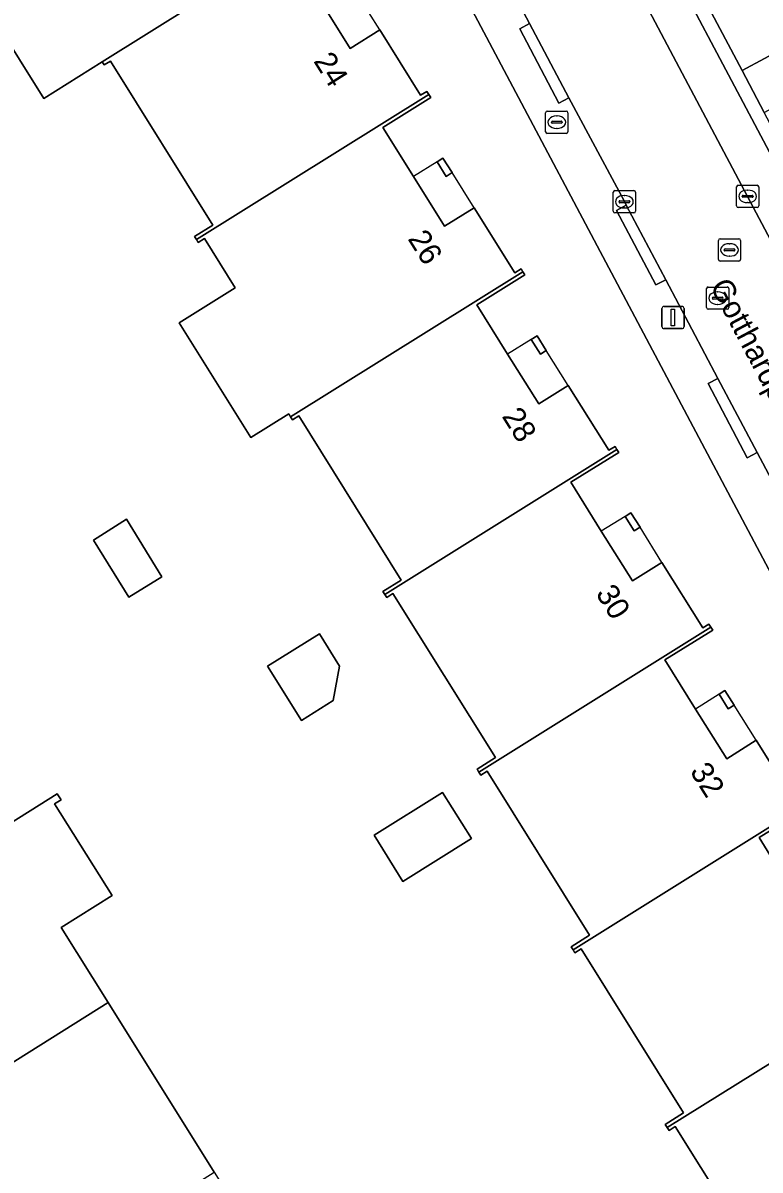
# Model space of a CAD drawing. Extents: x 158835 to 160077, y 386387 to 387778.
# Drawn here: x 159192.9 to 159226, y 387064.3 to 387115.8 of the extents above; entities that cross this region are included whole.
import ezdxf

# ---------------------------------------------------------------- set-up
doc = ezdxf.new("R2010")
doc.units = 0
for name, color, linetype in [('IMGEO_Berm_groen', 7, 'Continuous'), ('IMGEO_Brandkraan', 7, 'Continuous'), ('IMGEO_Erf', 7, 'Continuous'), ('IMGEO_Kolk', 7, 'Continuous'), ('IMGEO_Lichtmast', 7, 'Continuous'), ('IMGEO_Openbare_ruimte_label', 7, 'Continuous'), ('IMGEO_Pand', 7, 'Continuous'), ('IMGEO_Pand_nummerreeks', 7, 'Continuous'), ('IMGEO_Pand_overbouw', 7, 'Continuous'), ('IMGEO_Parkeervlak_open', 7, 'Continuous'), ('IMGEO_Rijbaan_lokaal_open', 7, 'Continuous'), ('IMGEO_Rioolput', 7, 'Continuous'), ('IMGEO_Voetpad_open', 7, 'Continuous')]:
    doc.layers.add(name, color=color, linetype=linetype)

msp = doc.modelspace()

# ---------------------------------------------------------------- linework, layer by layer
at = {"layer": 'IMGEO_Berm_groen'}
msp.add_lwpolyline([(159216.131, 387145.48), (159209.987, 387142.226), (159225.151, 387113.68), (159231.17, 387116.927), (159223.64, 387131.346), (159223.201, 387131.121)], close=True, dxfattribs=at)
at = {"layer": 'IMGEO_Brandkraan'}
for p, q in [((159216.334, 387110.937), (159216.334, 387111.789)), ((159216.409, 387111.863), (159217.261, 387111.863)), ((159217.335, 387111.789), (159217.335, 387110.937)), ((159216.593, 387111.357), (159216.593, 387111.369)), ((159217.031, 387111.32), (159216.633, 387111.32)), ((159216.636, 387111.406), (159217.034, 387111.406)), ((159216.822, 387111.643), (159216.847, 387111.643)), ((159217.077, 387111.369), (159217.077, 387111.357)), ((159217.261, 387110.863), (159216.409, 387110.863)), ((159216.845, 387111.083), (159216.82, 387111.083))]:
    msp.add_line(p, q, dxfattribs=at)
for points in [[(159216.334, 387110.937), (159216.334, 387111.789)], [(159216.409, 387111.863), (159217.261, 387111.863)], [(159217.335, 387111.789), (159217.335, 387110.937)], [(159217.261, 387110.863), (159216.409, 387110.863)]]:
    msp.add_lwpolyline(points, dxfattribs=at)
for centre, radius, start, end in [((159216.411, 387111.787), 0.0765, 91.552, 178.448), ((159216.411, 387111.787), 0.0765, 91.552, 178.448), ((159217.259, 387111.787), 0.0765, 1.552, 88.448), ((159217.259, 387111.787), 0.0765, 1.552, 88.448), ((159216.633, 387111.366), 0.0403, 85.8775, 175.7526), ((159216.63, 387111.356), 0.0366, 178.938, 274.7102), ((159217.034, 387111.363), 0.043, 264.8664, 352.4533), ((159217.038, 387111.368), 0.0386, 1.7309, 96.639), ((159216.411, 387110.939), 0.0765, 181.552, 268.448), ((159216.411, 387110.939), 0.0765, 181.552, 268.448), ((159217.259, 387110.939), 0.0765, 271.552, 358.448), ((159217.259, 387110.939), 0.0765, 271.552, 358.448)]:
    msp.add_arc(centre, radius, start, end, dxfattribs=at)
for centre, major_axis, ratio, start_param, end_param in [((159216.821, 387111.363), (-0.387, 0.002), 0.722429, 4.712389, 7.853982), ((159216.846, 387111.363), (-0.39, 0.002), 0.717154, 1.570796, 4.712389)]:
    msp.add_ellipse(centre, major_axis=major_axis, ratio=ratio, start_param=start_param, end_param=end_param, dxfattribs=at)
at = {"layer": 'IMGEO_Erf'}
for points in [[(159261.184, 387025.643), (159192.812, 387154.528)], [(159226.754, 387058.936), (159222.155, 387066.296), (159221.875, 387066.121), (159221.79, 387066.257), (159221.706, 387066.393), (159222.528, 387066.907), (159217.929, 387074.267), (159217.649, 387074.093), (159217.564, 387074.229), (159217.48, 387074.364), (159218.302, 387074.878), (159213.703, 387082.238), (159213.424, 387082.064), (159213.339, 387082.199), (159213.254, 387082.335), (159214.077, 387082.849), (159209.477, 387090.209), (159209.198, 387090.035), (159209.113, 387090.17), (159209.028, 387090.306), (159209.851, 387090.82), (159205.252, 387098.181), (159204.972, 387098.006), (159204.887, 387098.141), (159204.802, 387098.277), (159203.098, 387097.212), (159199.882, 387102.359), (159202.4, 387103.933), (159201.023, 387106.138), (159200.743, 387105.963), (159200.658, 387106.098), (159200.573, 387106.234), (159201.396, 387106.748), (159196.797, 387114.109), (159196.517, 387113.934), (159196.432, 387114.069), (159193.809, 387112.427), (159190.511, 387117.696)], [(159206.171, 387116.92), (159207.566, 387114.677), (159208.886, 387115.502), (159210.724, 387112.57), (159211.004, 387112.746), (159211.089, 387112.61), (159211.174, 387112.474), (159209.03, 387111.133), (159210.408, 387108.929), (159211.8, 387106.699), (159213.121, 387107.524), (159214.954, 387104.604), (159215.233, 387104.779), (159215.318, 387104.644), (159215.403, 387104.509), (159213.246, 387103.169), (159214.623, 387100.952), (159216.029, 387098.724), (159217.35, 387099.549), (159219.171, 387096.643), (159219.449, 387096.817), (159219.533, 387096.682), (159219.618, 387096.547), (159217.463, 387095.204), (159218.83, 387093.008), (159220.236, 387090.78), (159221.556, 387091.605), (159223.385, 387088.671), (159223.665, 387088.845), (159223.75, 387088.709), (159223.834, 387088.574), (159221.679, 387087.231), (159223.057, 387085.03), (159224.463, 387082.802), (159225.784, 387083.627), (159227.624, 387080.693)], [(159191.861, 387079.631), (159194.412, 387081.226), (159194.581, 387080.955), (159194.293, 387080.775), (159196.869, 387076.656), (159194.589, 387075.23), (159196.693, 387071.865), (159201.459, 387064.245), (159206.24, 387056.6), (159211.01, 387048.972), (159215.782, 387041.343), (159220.557, 387033.707), (159225.323, 387026.087)], [(159228.074, 387080.597), (159225.925, 387079.268), (159227.285, 387077.052)]]:
    msp.add_lwpolyline(points, dxfattribs=at)
for points in [[(159211.459, 387109.587), (159211.722, 387109.751), (159212.131, 387109.099), (159211.869, 387108.934)], [(159215.69, 387101.614), (159215.953, 387101.778), (159216.362, 387101.126), (159216.099, 387100.961)], [(159220.165, 387093.837), (159220.572, 387093.184), (159220.309, 387093.02), (159219.902, 387093.673)], [(159196.033, 387092.602), (159197.513, 387093.545), (159199.109, 387090.966), (159197.617, 387090.043)], [(159207.085, 387086.96), (159206.803, 387085.418), (159205.368, 387084.521), (159203.852, 387086.948), (159206.182, 387088.405)], [(159224.386, 387085.855), (159224.795, 387085.203), (159224.533, 387085.038), (159224.123, 387085.691)], [(159211.703, 387081.291), (159213.002, 387079.213), (159209.929, 387077.293), (159208.631, 387079.371)]]:
    msp.add_lwpolyline(points, close=True, dxfattribs=at)
at = {"layer": 'IMGEO_Kolk'}
for p, q in [((159219.369, 387107.368), (159219.369, 387108.22)), ((159219.444, 387108.294), (159220.296, 387108.294)), ((159220.37, 387108.22), (159220.37, 387107.368)), ((159224.903, 387107.609), (159224.903, 387108.461)), ((159224.978, 387108.535), (159225.83, 387108.535)), ((159225.391, 387108.315), (159225.416, 387108.315)), ((159225.904, 387108.461), (159225.904, 387107.609)), ((159219.628, 387107.788), (159219.628, 387107.8)), ((159220.066, 387107.751), (159219.668, 387107.751)), ((159219.671, 387107.837), (159220.069, 387107.837)), ((159219.857, 387108.074), (159219.882, 387108.074)), ((159220.112, 387107.8), (159220.112, 387107.788)), ((159225.162, 387108.029), (159225.162, 387108.041)), ((159225.6, 387107.992), (159225.202, 387107.992)), ((159225.205, 387108.078), (159225.603, 387108.078)), ((159225.414, 387107.755), (159225.389, 387107.755)), ((159225.646, 387108.041), (159225.646, 387108.029)), ((159220.296, 387107.294), (159219.444, 387107.294)), ((159219.88, 387107.514), (159219.855, 387107.514)), ((159225.83, 387107.535), (159224.978, 387107.535))]:
    msp.add_line(p, q, dxfattribs=at)
for points in [[(159219.369, 387107.368), (159219.369, 387108.22)], [(159219.444, 387108.294), (159220.296, 387108.294)], [(159220.37, 387108.22), (159220.37, 387107.368)], [(159224.903, 387107.609), (159224.903, 387108.461)], [(159224.978, 387108.535), (159225.83, 387108.535)], [(159225.904, 387108.461), (159225.904, 387107.609)], [(159220.296, 387107.294), (159219.444, 387107.294)], [(159225.83, 387107.535), (159224.978, 387107.535)]]:
    msp.add_lwpolyline(points, dxfattribs=at)
for centre, radius, start, end in [((159219.446, 387108.218), 0.0765, 91.552, 178.448), ((159219.446, 387108.218), 0.0765, 91.552, 178.448), ((159220.294, 387108.218), 0.0765, 1.552, 88.448), ((159220.294, 387108.218), 0.0765, 1.552, 88.448), ((159224.98, 387108.459), 0.0765, 91.552, 178.448), ((159224.98, 387108.459), 0.0765, 91.552, 178.448), ((159225.828, 387108.459), 0.0765, 1.552, 88.448), ((159225.828, 387108.459), 0.0765, 1.552, 88.448), ((159219.668, 387107.797), 0.0403, 85.8775, 175.7526), ((159219.665, 387107.787), 0.0366, 178.938, 274.7102), ((159220.069, 387107.794), 0.043, 264.8664, 352.4533), ((159220.073, 387107.799), 0.0386, 1.7309, 96.639), ((159224.98, 387107.611), 0.0765, 181.552, 268.448), ((159224.98, 387107.611), 0.0765, 181.552, 268.448), ((159225.202, 387108.038), 0.0403, 85.8775, 175.7526), ((159225.199, 387108.028), 0.0366, 178.938, 274.7102), ((159225.603, 387108.035), 0.043, 264.8664, 352.4533), ((159225.607, 387108.04), 0.0386, 1.7309, 96.639), ((159225.828, 387107.611), 0.0765, 271.552, 358.448), ((159225.828, 387107.611), 0.0765, 271.552, 358.448), ((159219.446, 387107.37), 0.0765, 181.552, 268.448), ((159219.446, 387107.37), 0.0765, 181.552, 268.448), ((159220.294, 387107.37), 0.0765, 271.552, 358.448), ((159220.294, 387107.37), 0.0765, 271.552, 358.448)]:
    msp.add_arc(centre, radius, start, end, dxfattribs=at)
for centre, major_axis, ratio, start_param, end_param in [((159225.39, 387108.035), (-0.387, 0.002), 0.722429, 4.712389, 7.853982), ((159225.415, 387108.035), (-0.39, 0.002), 0.717154, 1.570796, 4.712389), ((159219.856, 387107.794), (-0.387, 0.002), 0.722429, 4.712389, 7.853982), ((159219.881, 387107.794), (-0.39, 0.002), 0.717154, 1.570796, 4.712389)]:
    msp.add_ellipse(centre, major_axis=major_axis, ratio=ratio, start_param=start_param, end_param=end_param, dxfattribs=at)
at = {"layer": 'IMGEO_Lichtmast'}
for p, q in [((159221.556, 387102.199), (159221.556, 387102.999)), ((159221.556, 387102.999), (159221.556, 387102.199)), ((159221.656, 387103.099), (159222.446, 387103.099)), ((159222.446, 387103.099), (159221.656, 387103.099)), ((159222.546, 387102.999), (159222.546, 387102.199)), ((159222.546, 387102.199), (159222.546, 387102.999)), ((159222.446, 387102.099), (159221.656, 387102.099)), ((159221.656, 387102.099), (159222.446, 387102.099))]:
    msp.add_line(p, q, dxfattribs=at)
msp.add_lwpolyline([(159221.976, 387102.974), (159222.126, 387102.974), (159222.126, 387102.224), (159221.976, 387102.224), (159221.976, 387102.974)], dxfattribs=at)
for centre, start, end in [((159221.656, 387102.999), 90, 180), ((159221.656, 387102.999), 90, 180), ((159222.446, 387102.999), 0, 90), ((159222.446, 387102.999), 360, 90), ((159221.656, 387102.199), 180, 270), ((159221.656, 387102.199), 180, 270), ((159222.446, 387102.199), 270, 0), ((159222.446, 387102.199), 270, 0)]:
    msp.add_arc(centre, 0.1, start, end, dxfattribs=at)
at = {"layer": 'IMGEO_Pand'}
for points in [[(159204.667, 387123.466), (159203.347, 387122.641), (159201.966, 387124.874), (159200.584, 387127.072), (159202.714, 387128.412), (159202.629, 387128.548), (159192.211, 387122.033), (159192.296, 387121.897), (159192.576, 387122.071), (159193.962, 387119.853), (159190.511, 387117.696), (159193.809, 387112.427), (159196.432, 387114.069), (159206.858, 387120.595), (159206.773, 387120.73), (159206.495, 387120.555)], [(159208.886, 387115.502), (159207.566, 387114.677), (159206.171, 387116.92), (159204.804, 387119.145), (159206.943, 387120.46), (159206.858, 387120.595), (159196.432, 387114.069), (159196.517, 387113.934), (159196.797, 387114.109), (159201.396, 387106.748), (159200.573, 387106.234), (159200.658, 387106.098), (159211.089, 387112.61), (159211.004, 387112.746), (159210.724, 387112.57)], [(159213.121, 387107.524), (159211.8, 387106.699), (159210.408, 387108.929), (159209.03, 387111.133), (159211.174, 387112.474), (159211.089, 387112.61), (159200.658, 387106.098), (159200.743, 387105.963), (159201.023, 387106.138), (159202.4, 387103.933), (159199.882, 387102.359), (159203.098, 387097.212), (159204.802, 387098.277), (159204.887, 387098.141), (159215.318, 387104.644), (159215.233, 387104.779), (159214.954, 387104.604)], [(159211.722, 387109.751), (159211.459, 387109.587), (159211.869, 387108.934), (159212.131, 387109.099)], [(159217.35, 387099.549), (159216.029, 387098.724), (159214.623, 387100.952), (159213.246, 387103.169), (159215.403, 387104.509), (159215.318, 387104.644), (159204.887, 387098.141), (159204.972, 387098.006), (159205.252, 387098.181), (159209.851, 387090.82), (159209.028, 387090.306), (159209.113, 387090.17), (159219.533, 387096.682), (159219.449, 387096.817), (159219.171, 387096.643)], [(159215.953, 387101.778), (159215.69, 387101.614), (159216.099, 387100.961), (159216.362, 387101.126)], [(159221.556, 387091.605), (159220.236, 387090.78), (159218.83, 387093.008), (159217.463, 387095.204), (159219.618, 387096.547), (159219.533, 387096.682), (159209.113, 387090.17), (159209.198, 387090.035), (159209.477, 387090.209), (159214.077, 387082.849), (159213.254, 387082.335), (159213.339, 387082.199), (159223.75, 387088.709), (159223.665, 387088.845), (159223.385, 387088.671)], [(159220.165, 387093.837), (159219.902, 387093.673), (159220.309, 387093.02), (159220.572, 387093.184)], [(159196.033, 387092.602), (159197.617, 387090.043), (159199.109, 387090.966), (159197.513, 387093.545)], [(159225.784, 387083.627), (159224.463, 387082.802), (159223.057, 387085.03), (159221.679, 387087.231), (159223.834, 387088.574), (159223.75, 387088.709), (159213.339, 387082.199), (159213.424, 387082.064), (159213.703, 387082.238), (159218.302, 387074.878), (159217.48, 387074.364), (159217.564, 387074.229), (159227.989, 387080.733), (159227.904, 387080.868), (159227.624, 387080.693)], [(159203.852, 387086.948), (159205.368, 387084.521), (159206.803, 387085.418), (159207.085, 387086.96), (159206.182, 387088.405)], [(159224.386, 387085.855), (159224.123, 387085.691), (159224.533, 387085.038), (159224.795, 387085.203)], [(159194.589, 387075.23), (159196.869, 387076.656), (159194.293, 387080.775), (159194.581, 387080.955), (159194.412, 387081.226), (159191.861, 387079.631), (159191.946, 387079.495), (159182.069, 387073.317), (159182.153, 387073.181), (159183.756, 387074.181), (159185.132, 387071.975), (159186.523, 387069.743), (159185.199, 387068.918), (159187.029, 387065.984), (159186.758, 387065.814), (159186.843, 387065.678), (159196.693, 387071.865)], [(159208.631, 387079.371), (159209.929, 387077.293), (159213.002, 387079.213), (159211.703, 387081.291)], [(159230.012, 387075.65), (159228.691, 387074.825), (159227.285, 387077.052), (159225.925, 387079.268), (159228.074, 387080.597), (159227.989, 387080.733), (159217.564, 387074.229), (159217.649, 387074.093), (159217.929, 387074.267), (159222.528, 387066.907), (159221.706, 387066.393), (159221.79, 387066.257), (159232.217, 387072.75), (159232.132, 387072.886), (159231.852, 387072.71)], [(159234.24, 387067.673), (159232.92, 387066.848), (159231.509, 387069.082), (159230.151, 387071.292), (159232.302, 387072.614), (159232.217, 387072.75), (159221.79, 387066.257), (159221.875, 387066.121), (159222.155, 387066.296), (159226.754, 387058.936), (159225.932, 387058.422), (159226.016, 387058.286), (159236.446, 387064.776), (159236.361, 387064.912), (159236.08, 387064.736)], [(159196.693, 387071.865), (159186.843, 387065.678), (159186.927, 387065.543), (159188.521, 387066.546), (159189.896, 387064.362), (159191.297, 387062.136), (159189.968, 387061.3), (159191.799, 387058.351), (159191.527, 387058.181), (159191.612, 387058.044), (159201.459, 387064.245)]]:
    msp.add_lwpolyline(points, close=True, dxfattribs=at)
at = {"layer": 'IMGEO_Pand_overbouw'}
for points in [[(159207.898, 387117.078), (159207.489, 387117.73), (159207.225, 387117.568), (159206.171, 387116.92), (159207.566, 387114.677), (159208.886, 387115.502)], [(159212.131, 387109.099), (159211.722, 387109.751), (159211.459, 387109.587), (159210.408, 387108.929), (159211.8, 387106.699), (159213.121, 387107.524)], [(159216.362, 387101.126), (159215.953, 387101.778), (159215.69, 387101.614), (159214.623, 387100.952), (159216.029, 387098.724), (159217.35, 387099.549)], [(159220.572, 387093.184), (159220.165, 387093.837), (159219.902, 387093.673), (159218.83, 387093.008), (159220.236, 387090.78), (159221.556, 387091.605)], [(159224.795, 387085.203), (159224.386, 387085.855), (159224.123, 387085.691), (159223.057, 387085.03), (159224.463, 387082.802), (159225.784, 387083.627)]]:
    msp.add_lwpolyline(points, close=True, dxfattribs=at)
at = {"layer": 'IMGEO_Parkeervlak_open'}
for points in [[(159268.384, 387030.839), (159217.085, 387127.542)], [(159216.713, 387124.427), (159225.399, 387108.034), (159237.811, 387084.633), (159248.115, 387065.172), (159257.979, 387046.591)]]:
    msp.add_lwpolyline(points, dxfattribs=at)
at = {"layer": 'IMGEO_Rijbaan_lokaal_open'}
for points in [[(159257.979, 387046.591), (159248.115, 387065.172), (159237.811, 387084.633), (159225.399, 387108.034), (159216.713, 387124.427)], [(159213.276, 387120.222), (159215.613, 387115.79), (159217.374, 387112.457), (159219.855, 387107.834), (159219.95, 387107.637), (159221.723, 387104.295), (159224.064, 387099.868), (159225.827, 387096.54), (159228.412, 387091.668), (159230.181, 387088.351), (159232.537, 387083.923), (159234.3, 387080.597), (159234.872, 387079.512), (159236.866, 387075.757), (159238.628, 387072.438), (159240.974, 387068.001), (159242.753, 387064.674), (159243.322, 387063.566)]]:
    msp.add_lwpolyline(points, dxfattribs=at)
at = {"layer": 'IMGEO_Rioolput'}
for p, q in [((159224.087, 387105.206), (159224.087, 387106.058)), ((159224.162, 387106.132), (159225.014, 387106.132)), ((159225.088, 387106.058), (159225.088, 387105.206)), ((159224.346, 387105.626), (159224.346, 387105.638)), ((159224.784, 387105.589), (159224.386, 387105.589)), ((159224.389, 387105.675), (159224.787, 387105.675)), ((159224.575, 387105.912), (159224.6, 387105.912)), ((159224.83, 387105.638), (159224.83, 387105.626)), ((159225.014, 387105.132), (159224.162, 387105.132)), ((159224.598, 387105.352), (159224.573, 387105.352)), ((159223.557, 387103.042), (159223.557, 387103.894)), ((159223.632, 387103.968), (159224.484, 387103.968)), ((159223.859, 387103.511), (159224.257, 387103.511)), ((159224.045, 387103.748), (159224.07, 387103.748)), ((159224.558, 387103.894), (159224.558, 387103.042)), ((159224.484, 387102.968), (159223.632, 387102.968)), ((159223.816, 387103.462), (159223.816, 387103.474)), ((159224.254, 387103.425), (159223.856, 387103.425)), ((159224.068, 387103.188), (159224.043, 387103.188)), ((159224.3, 387103.474), (159224.3, 387103.462))]:
    msp.add_line(p, q, dxfattribs=at)
for points in [[(159224.087, 387105.206), (159224.087, 387106.058)], [(159224.162, 387106.132), (159225.014, 387106.132)], [(159225.088, 387106.058), (159225.088, 387105.206)], [(159225.014, 387105.132), (159224.162, 387105.132)], [(159223.557, 387103.042), (159223.557, 387103.894)], [(159223.632, 387103.968), (159224.484, 387103.968)], [(159224.558, 387103.894), (159224.558, 387103.042)], [(159224.484, 387102.968), (159223.632, 387102.968)]]:
    msp.add_lwpolyline(points, dxfattribs=at)
for centre, radius, start, end in [((159224.164, 387106.056), 0.0765, 91.552, 178.448), ((159224.164, 387106.056), 0.0765, 91.552, 178.448), ((159225.012, 387106.056), 0.0765, 1.552, 88.448), ((159225.012, 387106.056), 0.0765, 1.552, 88.448), ((159224.386, 387105.635), 0.0403, 85.8775, 175.7526), ((159224.383, 387105.625), 0.0366, 178.938, 274.7102), ((159224.787, 387105.632), 0.043, 264.8664, 352.4533), ((159224.791, 387105.637), 0.0386, 1.7309, 96.639), ((159224.164, 387105.208), 0.0765, 181.552, 268.448), ((159224.164, 387105.208), 0.0765, 181.552, 268.448), ((159225.012, 387105.208), 0.0765, 271.552, 358.448), ((159225.012, 387105.208), 0.0765, 271.552, 358.448), ((159223.634, 387103.892), 0.0765, 91.552, 178.448), ((159223.634, 387103.892), 0.0765, 91.552, 178.448), ((159223.856, 387103.471), 0.0403, 85.8775, 175.7526), ((159224.261, 387103.473), 0.0386, 1.7309, 96.639), ((159224.482, 387103.892), 0.0765, 1.552, 88.448), ((159224.482, 387103.892), 0.0765, 1.552, 88.448), ((159223.634, 387103.044), 0.0765, 181.552, 268.448), ((159223.634, 387103.044), 0.0765, 181.552, 268.448), ((159223.853, 387103.461), 0.0366, 178.938, 274.7102), ((159224.257, 387103.468), 0.043, 264.8664, 352.4533), ((159224.482, 387103.044), 0.0765, 271.552, 358.448), ((159224.482, 387103.044), 0.0765, 271.552, 358.448)]:
    msp.add_arc(centre, radius, start, end, dxfattribs=at)
for centre, major_axis, ratio, start_param, end_param in [((159224.574, 387105.632), (-0.387, 0.002), 0.722429, 4.712389, 7.853982), ((159224.599, 387105.632), (-0.39, 0.002), 0.717154, 1.570796, 4.712389), ((159224.044, 387103.468), (-0.387, 0.002), 0.722429, 4.712389, 7.853982), ((159224.069, 387103.468), (-0.39, 0.002), 0.717154, 1.570796, 4.712389)]:
    msp.add_ellipse(centre, major_axis=major_axis, ratio=ratio, start_param=start_param, end_param=end_param, dxfattribs=at)
at = {"layer": 'IMGEO_Voetpad_open'}
for points in [[(159192.812, 387154.528), (159261.184, 387025.643)], [(159270.438, 387028.309), (159226.137, 387111.804), (159225.151, 387113.68), (159209.987, 387142.226)], [(159217.085, 387127.542), (159268.384, 387030.839)], [(159228.412, 387091.668), (159225.827, 387096.54), (159225.386, 387096.306), (159223.623, 387099.634), (159224.064, 387099.868), (159221.723, 387104.295), (159221.282, 387104.061), (159219.509, 387107.403), (159219.95, 387107.637), (159219.855, 387107.834), (159217.374, 387112.457), (159216.932, 387112.224), (159215.171, 387115.557), (159215.613, 387115.79), (159213.276, 387120.222)]]:
    msp.add_lwpolyline(points, dxfattribs=at)
for points in [[(159226.137, 387111.804), (159232.161, 387115.069), (159231.17, 387116.927), (159225.151, 387113.68)], [(159217.374, 387112.457), (159215.613, 387115.79), (159215.171, 387115.557), (159216.932, 387112.224)], [(159219.95, 387107.637), (159219.509, 387107.403), (159221.282, 387104.061), (159221.723, 387104.295)], [(159225.827, 387096.54), (159224.064, 387099.868), (159223.623, 387099.634), (159225.386, 387096.306)]]:
    msp.add_lwpolyline(points, close=True, dxfattribs=at)

# ---------------------------------------------------------------- texts
at = {"layer": 'IMGEO_Openbare_ruimte_label'}
msp.add_text('Gotthardpas', height=1, rotation=297.8973, dxfattribs=at).set_placement((159223.691, 387104.019))
at = {"layer": 'IMGEO_Pand_nummerreeks'}
for s, rotation, p in [('24', 302.0854, (159205.889, 387114.108)), ('26', 302.1255, (159210.12, 387106.133)), ('28', 302.074, (159214.346, 387098.168)), ('30', 301.9365, (159218.556, 387090.218)), ('32', 302.0969, (159222.786, 387082.234))]:
    msp.add_text(s, height=1, rotation=rotation, dxfattribs=at).set_placement(p)

doc.saveas('drawing.dxf')
